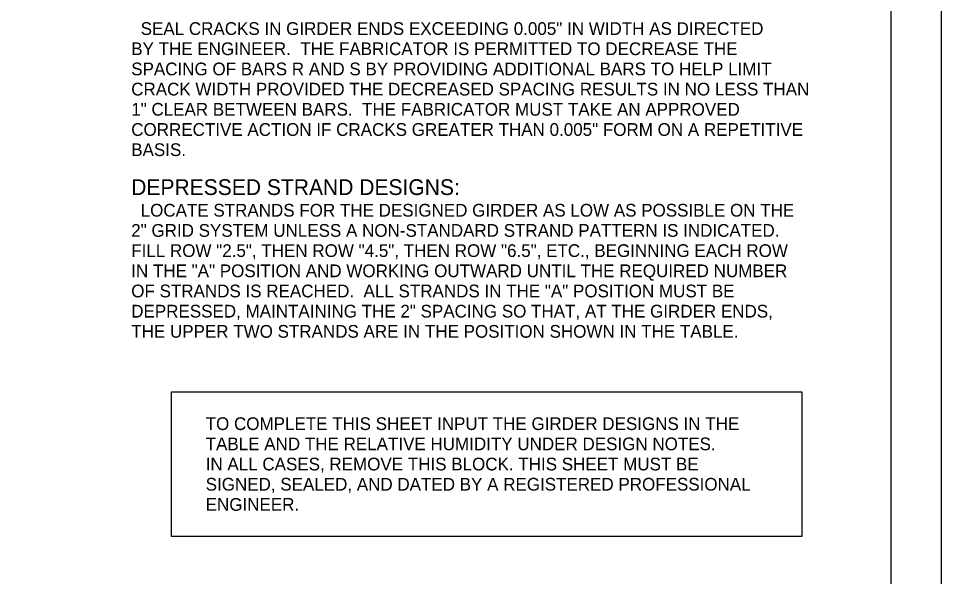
# Model space of a CAD drawing. Extents: x 998.6 to 1033.3, y 1000 to 1011.
# Drawn here: x 1012.425 to 1017, y 1002.765 to 1005.529 of the extents above; entities that cross this region are included whole.
import ezdxf

# ---------------------------------------------------------------- set-up
doc = ezdxf.new("R2010")
doc.units = 0
for name, color, linetype in [('D_BATCH_PLOT', 7, 'Continuous'), ('D_SHEET', 7, 'Continuous'), ('Working Level 1', 7, 'Continuous')]:
    doc.layers.add(name, color=color, linetype=linetype)

msp = doc.modelspace()

# ---------------------------------------------------------------- linework, layer by layer
at = {"layer": 'D_BATCH_PLOT'}
msp.add_lwpolyline([(1000, 1000), (1017, 1000), (1017, 1011), (1000, 1011)], close=True, dxfattribs=at)
at = {"layer": 'D_SHEET'}
for p, q in [((1017, 1000), (1017, 1011)), ((1016.75, 1000.25), (1016.75, 1010.75))]:
    msp.add_line(p, q, dxfattribs=at)
at = {"layer": 'Working Level 1'}
msp.add_lwpolyline([(1013.1836, 1003.6797), (1016.3068, 1003.6797), (1016.3068, 1002.9635), (1013.1836, 1002.9635)], close=True, dxfattribs=at)

# ---------------------------------------------------------------- texts
for s, height, p in [('  SEAL CRACKS IN GIRDER ENDS EXCEEDING 0.005" IN WIDTH AS DIRECTED ', 0.063, (1012.9837, 1005.4475)), ('BY THE ENGINEER.  THE FABRICATOR IS PERMITTED TO DECREASE THE ', 0.063, (1012.9837, 1005.3475)), ('SPACING OF BARS R AND S BY PROVIDING ADDITIONAL BARS TO HELP LIMIT ', 0.063, (1012.9837, 1005.2475)), ('CRACK WIDTH PROVIDED THE DECREASED SPACING RESULTS IN NO LESS THAN ', 0.063, (1012.9837, 1005.1475)), ('1" CLEAR BETWEEN BARS.  THE FABRICATOR MUST TAKE AN APPROVED ', 0.063, (1012.9837, 1005.0475)), ('CORRECTIVE ACTION IF CRACKS GREATER THAN 0.005" FORM ON A REPETITIVE ', 0.063, (1012.9837, 1004.9475)), ('BASIS.', 0.063, (1012.9837, 1004.8475)), ('DEPRESSED STRAND DESIGNS:', 0.078, (1012.9837, 1004.6545)), ('  LOCATE STRANDS FOR THE DESIGNED GIRDER AS LOW AS POSSIBLE ON THE', 0.063, (1012.9837, 1004.5475)), ('2" GRID SYSTEM UNLESS A NON-STANDARD STRAND PATTERN IS INDICATED.', 0.063, (1012.9837, 1004.4475)), ('FILL ROW "2.5", THEN ROW "4.5", THEN ROW "6.5", ETC., BEGINNING EACH ROW', 0.063, (1012.9837, 1004.3475)), ('IN THE "A" POSITION AND WORKING OUTWARD UNTIL THE REQUIRED NUMBER', 0.063, (1012.9837, 1004.2475)), ('OF STRANDS IS REACHED.  ALL STRANDS IN THE "A" POSITION MUST BE', 0.063, (1012.9837, 1004.1475)), ('DEPRESSED, MAINTAINING THE 2" SPACING SO THAT, AT THE GIRDER ENDS,', 0.063, (1012.9837, 1004.0475)), ('THE UPPER TWO STRANDS ARE IN THE POSITION SHOWN IN THE TABLE.', 0.063, (1012.9837, 1003.9475)), ('TO COMPLETE THIS SHEET INPUT THE GIRDER DESIGNS IN THE ', 0.063, (1013.3527, 1003.4902)), ('TABLE AND THE RELATIVE HUMIDITY UNDER DESIGN NOTES. ', 0.063, (1013.3527, 1003.3902)), ('IN ALL CASES, REMOVE THIS BLOCK. THIS SHEET MUST BE ', 0.063, (1013.3527, 1003.2902)), ('SIGNED, SEALED, AND DATED BY A REGISTERED PROFESSIONAL ', 0.063, (1013.3527, 1003.1902)), ('ENGINEER. ', 0.063, (1013.3527, 1003.0902))]:
    msp.add_text(s, height=height, dxfattribs=at).set_placement(p)

doc.saveas('drawing.dxf')
